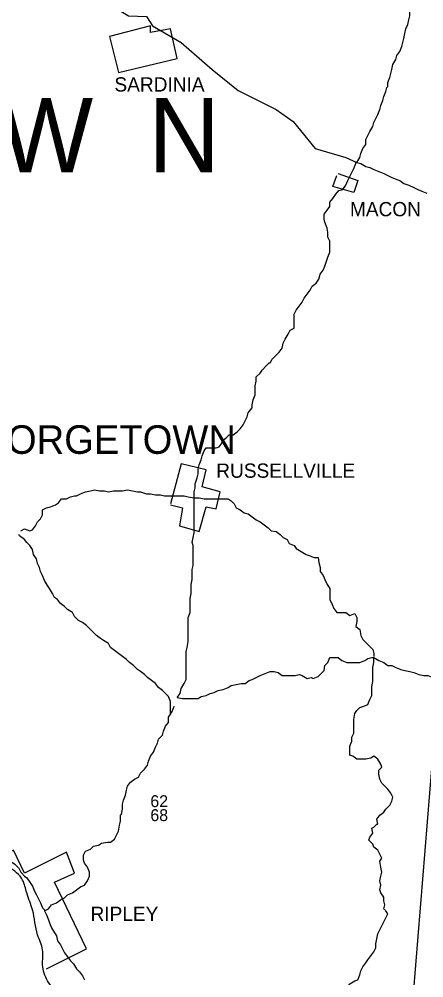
# Model space of a CAD drawing. Extents: x 0 to 34, y 0 to 22.
# Drawn here: x 3.025 to 3.578, y 16.44 to 17.75 of the extents above; entities that cross this region are included whole.
import ezdxf

# ---------------------------------------------------------------- set-up
doc = ezdxf.new("R2010")
doc.units = 0
doc.layers.add('Default', color=7, linetype='Continuous')
doc.layers.add('TR_Turning_Path1', color=7, linetype='Continuous')

msp = doc.modelspace()

# ---------------------------------------------------------------- linework, layer by layer
at = {"layer": 'Default'}
for points in [[(3.1104, 17.794), (3.1308, 17.779), (3.1499, 17.7694), (3.1744, 17.7544), (3.199, 17.7531), (3.2072, 17.7408), (3.2467, 17.7176), (3.289, 17.6808), (3.3244, 17.6522), (3.3762, 17.6263), (3.3994, 17.6099), (3.4294, 17.5731), (3.4717, 17.5608), (3.4867, 17.554)], [(3.5289, 17.6576), (3.5289, 17.6631), (3.5316, 17.6699), (3.533, 17.6754), (3.5344, 17.6808), (3.5357, 17.6876), (3.5398, 17.6945), (3.5412, 17.6999), (3.5453, 17.7054), (3.548, 17.7122), (3.5494, 17.7176), (3.5507, 17.7231), (3.5521, 17.7299), (3.5535, 17.7367), (3.5562, 17.7422), (3.5576, 17.749), (3.5589, 17.7544), (3.5589, 17.7613), (3.5603, 17.7667), (3.5603, 17.7735), (3.563, 17.7804), (3.5644, 17.7872), (3.5644, 17.7913)], [(3.6789, 17.7858), (3.6516, 17.4749), (3.5985, 16.8491), (3.5507, 16.2615), (3.5412, 16.0883), (3.5398, 16.0652)], [(3.2317, 17.7367), (3.2044, 17.7313), (3.2044, 17.7408), (3.1485, 17.7258), (3.1608, 17.6767), (3.2412, 17.6958), (3.2317, 17.7367)], [(3.4867, 17.554), (3.4907, 17.5608), (3.4921, 17.5663), (3.4948, 17.5731), (3.4989, 17.5786), (3.4989, 17.5854), (3.5017, 17.5908), (3.5044, 17.5963), (3.5085, 17.6031), (3.5098, 17.6086), (3.5126, 17.614), (3.5153, 17.6195), (3.518, 17.6263), (3.5194, 17.6317), (3.5221, 17.6386), (3.5235, 17.644), (3.5262, 17.6508), (3.5276, 17.6563), (3.5289, 17.6576)], [(3.4498, 17.4327), (3.4498, 17.4395), (3.4498, 17.4463), (3.4471, 17.4518), (3.4471, 17.4586), (3.4458, 17.464), (3.443, 17.4722), (3.4417, 17.4763), (3.4417, 17.4831), (3.4458, 17.4886), (3.4498, 17.494), (3.4498, 17.4995), (3.4539, 17.5049), (3.458, 17.5104), (3.4621, 17.5158), (3.4676, 17.5172), (3.4717, 17.5227), (3.4744, 17.5295), (3.4771, 17.5349), (3.4798, 17.5404), (3.4826, 17.5458), (3.4853, 17.5527), (3.4853, 17.554), (3.4867, 17.554)], [(3.4867, 17.554), (3.4921, 17.5527), (3.4989, 17.5486), (3.5044, 17.5472), (3.5098, 17.5445), (3.5167, 17.5418), (3.5235, 17.539), (3.5289, 17.5363), (3.5344, 17.5336), (3.5412, 17.5308), (3.5453, 17.5295), (3.5507, 17.5254), (3.5576, 17.5227), (3.5644, 17.5199), (3.5698, 17.5172), (3.5753, 17.5145), (3.5821, 17.5118)], [(3.4608, 17.539), (3.488, 17.5295), (3.4826, 17.5131), (3.4539, 17.5213), (3.4594, 17.5363)], [(3.368, 17.28), (3.3708, 17.2854), (3.3762, 17.2909), (3.3803, 17.295), (3.3844, 17.3004), (3.3858, 17.3072), (3.3885, 17.3127), (3.3926, 17.3195), (3.3953, 17.325), (3.4008, 17.3277), (3.4008, 17.3331), (3.4008, 17.34), (3.4008, 17.3468), (3.4035, 17.3522), (3.4076, 17.3577), (3.4117, 17.3631), (3.4144, 17.3686), (3.4185, 17.3741), (3.4226, 17.3795), (3.4253, 17.385), (3.4308, 17.389), (3.4348, 17.3945), (3.4362, 17.4013), (3.4403, 17.4068), (3.443, 17.4122), (3.4444, 17.4177), (3.4471, 17.4245), (3.4498, 17.4313), (3.4498, 17.4327), (3.4498, 17.4327)], [(3.3026, 17.1736), (3.308, 17.1777), (3.3121, 17.1818), (3.3176, 17.1818), (3.323, 17.1859), (3.3271, 17.19), (3.3312, 17.1954), (3.334, 17.2009), (3.3367, 17.2064), (3.338, 17.2118), (3.3435, 17.2186), (3.3435, 17.2227), (3.3449, 17.2295), (3.3476, 17.2363), (3.3476, 17.2418), (3.3476, 17.2486), (3.3489, 17.2554), (3.3489, 17.2609), (3.3544, 17.2663), (3.3571, 17.2704), (3.3626, 17.2759), (3.3667, 17.28), (3.368, 17.28)], [(3.2644, 17.0959), (3.2644, 17.1041), (3.2658, 17.1095), (3.2658, 17.115), (3.2685, 17.1232), (3.2699, 17.1286), (3.2699, 17.1355), (3.2712, 17.1409), (3.274, 17.1477), (3.2753, 17.1532), (3.2781, 17.16), (3.2808, 17.1641), (3.2876, 17.1641), (3.2944, 17.1641), (3.2985, 17.1654), (3.3026, 17.1709), (3.3026, 17.1723), (3.3026, 17.1736)], [(3.2317, 17.0864), (3.2481, 17.0823), (3.244, 17.0577), (3.2712, 17.0496), (3.2808, 17.0836), (3.2944, 17.0809), (3.2999, 17.1041), (3.2753, 17.1109), (3.2808, 17.1341), (3.2467, 17.1423), (3.2317, 17.0877)], [(3.1035, 17.0986), (3.109, 17.1014), (3.1158, 17.1041), (3.1226, 17.1055), (3.1281, 17.1068), (3.1349, 17.1055), (3.1417, 17.1055), (3.1472, 17.1041), (3.154, 17.1055), (3.1608, 17.1055), (3.1663, 17.1055), (3.1731, 17.1068), (3.1799, 17.1055), (3.1867, 17.1041), (3.1908, 17.1041), (3.199, 17.1014), (3.2044, 17.1014), (3.2112, 17.1), (3.2181, 17.1), (3.2235, 17.0986), (3.2317, 17.0986), (3.2371, 17.0986), (3.244, 17.0986), (3.2508, 17.0986), (3.2562, 17.0973), (3.2644, 17.0959), (3.2644, 17.0959)], [(3.1035, 17.0986), (3.109, 17.1014), (3.1158, 17.1041), (3.1226, 17.1055), (3.1281, 17.1068), (3.1349, 17.1055), (3.1417, 17.1055), (3.1472, 17.1041), (3.154, 17.1055), (3.1608, 17.1055), (3.1663, 17.1055), (3.1731, 17.1068), (3.1799, 17.1055), (3.1867, 17.1041), (3.1908, 17.1041), (3.199, 17.1014), (3.2044, 17.1014), (3.2112, 17.1), (3.2181, 17.1), (3.2235, 17.0986), (3.2317, 17.0986), (3.2371, 17.0986), (3.244, 17.0986), (3.2508, 17.0986), (3.2562, 17.0973), (3.2644, 17.0959), (3.2644, 17.0959)], [(3.0272, 17.0509), (3.0326, 17.0536), (3.0395, 17.0509), (3.0435, 17.0523), (3.0476, 17.0577), (3.0504, 17.0632), (3.0545, 17.0673), (3.0572, 17.0727), (3.0572, 17.0796), (3.0626, 17.0823), (3.0681, 17.0836), (3.0749, 17.0864), (3.079, 17.0891), (3.0831, 17.0946), (3.0899, 17.0946), (3.0954, 17.0973), (3.1008, 17.0986), (3.1035, 17.0986)], [(3.0272, 17.0509), (3.0326, 17.0536), (3.0395, 17.0509), (3.0435, 17.0523), (3.0476, 17.0577), (3.0504, 17.0632), (3.0545, 17.0673), (3.0572, 17.0727), (3.0572, 17.0796), (3.0626, 17.0823), (3.0681, 17.0836), (3.0749, 17.0864), (3.079, 17.0891), (3.0831, 17.0946), (3.0899, 17.0946), (3.0954, 17.0973), (3.1008, 17.0986), (3.1035, 17.0986)], [(3.2412, 16.8232), (3.2453, 16.8287), (3.2467, 16.8355), (3.2508, 16.8423), (3.2535, 16.8478), (3.2535, 16.8532), (3.2535, 16.86), (3.2535, 16.8669), (3.2535, 16.8737), (3.2535, 16.8791), (3.2535, 16.8859), (3.2549, 16.8914), (3.2562, 16.8996), (3.2562, 16.9064), (3.2562, 16.9119), (3.2562, 16.9187), (3.2562, 16.9269), (3.2562, 16.9323), (3.259, 16.9391), (3.259, 16.9446), (3.259, 16.9514), (3.259, 16.9582), (3.2603, 16.965), (3.2603, 16.9718), (3.2603, 16.9773), (3.2617, 16.9841), (3.2617, 16.9896), (3.2617, 16.9977), (3.2631, 17.0032), (3.2631, 17.0114), (3.2631, 17.0168), (3.2631, 17.0223), (3.2631, 17.0305), (3.2617, 17.0346), (3.2631, 17.0414), (3.2644, 17.0482), (3.2644, 17.055), (3.2644, 17.0618), (3.2644, 17.0673), (3.2644, 17.0741), (3.2644, 17.0809), (3.2644, 17.0877), (3.2644, 17.0946), (3.2644, 17.0959)], [(3.2644, 17.0959), (3.2712, 17.0959), (3.2781, 17.0946), (3.2835, 17.0946), (3.289, 17.0946), (3.2971, 17.0946), (3.3026, 17.0946), (3.3108, 17.0946), (3.3149, 17.0918), (3.319, 17.0877), (3.3217, 17.0823), (3.3271, 17.0796), (3.3326, 17.0755), (3.338, 17.0741), (3.3435, 17.07), (3.3489, 17.0659), (3.3544, 17.0632), (3.3599, 17.0591), (3.3653, 17.055), (3.3694, 17.0509), (3.3762, 17.0496), (3.3817, 17.0455), (3.3858, 17.0414), (3.3912, 17.0387), (3.3939, 17.0332), (3.3939, 17.0332)], [(3.1226, 16.9159), (3.1172, 16.9214), (3.1117, 16.9255), (3.1063, 16.9282), (3.1008, 16.9337), (3.0981, 16.9391), (3.0913, 16.9432), (3.0872, 16.9473), (3.0817, 16.9514), (3.0776, 16.9568), (3.0735, 16.9596), (3.0708, 16.965), (3.0667, 16.9718), (3.064, 16.9759), (3.0599, 16.9828), (3.0572, 16.9896), (3.0545, 16.995), (3.0531, 17.0005), (3.0504, 17.0059), (3.049, 17.0127), (3.0449, 17.0182), (3.0435, 17.025), (3.0395, 17.0305), (3.0354, 17.0346), (3.0326, 17.0387), (3.0258, 17.0441), (3.0245, 17.0455)], [(3.3939, 17.0332), (3.4008, 17.0305), (3.4035, 17.0264), (3.4103, 17.0223), (3.4171, 17.0182), (3.4212, 17.0168), (3.428, 17.0141), (3.4335, 17.0141), (3.4348, 17.0073), (3.4362, 17.0005), (3.4362, 16.995), (3.4403, 16.9896), (3.443, 16.9841), (3.4458, 16.9773), (3.4498, 16.9718), (3.4498, 16.965), (3.4498, 16.9637)], [(3.4498, 16.9637), (3.4498, 16.9568), (3.4526, 16.95), (3.4553, 16.9446), (3.4594, 16.9391), (3.4662, 16.9391), (3.4717, 16.9391), (3.4771, 16.935), (3.4839, 16.9378), (3.4867, 16.9323), (3.4867, 16.9269), (3.4853, 16.92), (3.4907, 16.9159), (3.4921, 16.9078), (3.4948, 16.9023), (3.4989, 16.8982), (3.503, 16.8941), (3.5085, 16.8887), (3.5098, 16.8832), (3.5098, 16.8791)], [(3.2317, 16.8001), (3.2317, 16.8055), (3.2317, 16.811), (3.2317, 16.8178), (3.229, 16.8246), (3.2249, 16.8287), (3.2208, 16.8328), (3.2153, 16.8369), (3.2112, 16.8423), (3.2058, 16.8464), (3.2003, 16.8505), (3.1962, 16.8546), (3.1908, 16.8587), (3.1867, 16.8614), (3.1812, 16.8669), (3.1758, 16.8709), (3.1717, 16.875), (3.1663, 16.8791), (3.1608, 16.8832), (3.1553, 16.8873), (3.1499, 16.8914), (3.1472, 16.8969), (3.1403, 16.9009), (3.1363, 16.9037), (3.1308, 16.9078), (3.1253, 16.9132), (3.1226, 16.9159), (3.1226, 16.9159)], [(3.4267, 16.8491), (3.4335, 16.8519), (3.4362, 16.8546), (3.4417, 16.86), (3.443, 16.8669), (3.4471, 16.8709), (3.4498, 16.8778), (3.4553, 16.8778), (3.4608, 16.8778), (3.4662, 16.8737), (3.473, 16.8709), (3.4771, 16.8709), (3.4853, 16.8709), (3.4907, 16.8709), (3.4976, 16.8737), (3.5017, 16.8764), (3.5071, 16.8778), (3.5098, 16.8778)], [(3.4771, 16.7442), (3.4771, 16.751), (3.4771, 16.7564), (3.4798, 16.7632), (3.4798, 16.7687), (3.4826, 16.7741), (3.4826, 16.781), (3.4826, 16.7878), (3.4826, 16.7932), (3.4839, 16.8014), (3.4867, 16.8055), (3.4907, 16.8096), (3.4962, 16.811), (3.5017, 16.8137), (3.5044, 16.8205), (3.5071, 16.826), (3.5071, 16.8328), (3.5071, 16.8382), (3.5085, 16.845), (3.5085, 16.8505), (3.5085, 16.8587), (3.5085, 16.8641), (3.5098, 16.8709), (3.5098, 16.8764), (3.5098, 16.8778), (3.5098, 16.8778)], [(3.5098, 16.8778), (3.5167, 16.8737), (3.5235, 16.8709), (3.5289, 16.8669), (3.5344, 16.8669), (3.5398, 16.8641), (3.5466, 16.8614), (3.5521, 16.86), (3.5589, 16.8587), (3.5644, 16.8573), (3.5712, 16.8546), (3.578, 16.8532), (3.5835, 16.8532), (3.5903, 16.8505), (3.5971, 16.8491), (3.5985, 16.8491)], [(3.3435, 16.8478), (3.3489, 16.8505), (3.3544, 16.8532), (3.3612, 16.856), (3.368, 16.8587), (3.3735, 16.8587), (3.3789, 16.8573), (3.3844, 16.8532), (3.3912, 16.8532), (3.3953, 16.8532), (3.4021, 16.8532), (3.4076, 16.8546), (3.4117, 16.8532), (3.4185, 16.8491), (3.4239, 16.8505), (3.4267, 16.8491), (3.4267, 16.8491)], [(3.2412, 16.8232), (3.2481, 16.8219), (3.2562, 16.8219), (3.2617, 16.8219), (3.2699, 16.8219), (3.274, 16.8246), (3.2808, 16.826), (3.2862, 16.8287), (3.2917, 16.83), (3.2971, 16.8328), (3.304, 16.8341), (3.3108, 16.8369), (3.3149, 16.8396), (3.3217, 16.841), (3.3285, 16.8423), (3.334, 16.8423), (3.3394, 16.8464), (3.3435, 16.8478), (3.3435, 16.8478)], [(3.2317, 16.8001), (3.2344, 16.8041), (3.2371, 16.811), (3.2371, 16.811)], [(3.1649, 16.6637), (3.1663, 16.6705), (3.1663, 16.6773), (3.1676, 16.6828), (3.1703, 16.6896), (3.1717, 16.6964), (3.1731, 16.7019), (3.1772, 16.7073), (3.1826, 16.7114), (3.1881, 16.7142), (3.1908, 16.7196), (3.1962, 16.7251), (3.2003, 16.7305), (3.2017, 16.736), (3.2044, 16.7428), (3.2085, 16.7482), (3.2112, 16.7551), (3.214, 16.7605), (3.2153, 16.766), (3.2208, 16.7714), (3.2222, 16.7769), (3.2249, 16.7837), (3.229, 16.7891), (3.229, 16.796), (3.2317, 16.8001)], [(3.1649, 16.6637), (3.1663, 16.6705), (3.1663, 16.6773), (3.1676, 16.6828), (3.1703, 16.6896), (3.1717, 16.6964), (3.1731, 16.7019), (3.1772, 16.7073), (3.1826, 16.7114), (3.1881, 16.7142), (3.1908, 16.7196), (3.1962, 16.7251), (3.2003, 16.7305), (3.2017, 16.736), (3.2044, 16.7428), (3.2085, 16.7482), (3.2112, 16.7551), (3.214, 16.7605), (3.2153, 16.766), (3.2208, 16.7714), (3.2222, 16.7769), (3.2249, 16.7837), (3.229, 16.7891), (3.229, 16.796), (3.2317, 16.8001)], [(3.5153, 16.6501), (3.5139, 16.6569), (3.518, 16.6623), (3.5235, 16.6664), (3.5262, 16.6705), (3.5316, 16.676), (3.5344, 16.6814), (3.5357, 16.6869), (3.533, 16.6923), (3.5289, 16.6978), (3.5248, 16.7019), (3.5207, 16.706), (3.518, 16.7114), (3.5167, 16.7182), (3.5167, 16.7237), (3.5207, 16.7278), (3.5194, 16.7319), (3.5153, 16.7387), (3.5098, 16.7428), (3.5057, 16.7401), (3.4989, 16.7387), (3.4935, 16.7387), (3.4867, 16.7387), (3.4812, 16.7428), (3.4771, 16.7442)], [(3.1213, 16.5846), (3.1185, 16.5914), (3.1144, 16.5969), (3.1131, 16.601), (3.1131, 16.6078), (3.1158, 16.6133), (3.1226, 16.616), (3.1267, 16.6201), (3.1335, 16.6214), (3.1376, 16.6242), (3.1458, 16.6255), (3.1499, 16.6255), (3.1553, 16.6296), (3.1581, 16.6351), (3.1608, 16.6405), (3.1622, 16.6487), (3.1635, 16.6542), (3.1635, 16.6623), (3.1649, 16.6637), (3.1649, 16.6637)], [(3.1213, 16.5846), (3.1185, 16.5914), (3.1144, 16.5969), (3.1131, 16.601), (3.1131, 16.6078), (3.1158, 16.6133), (3.1226, 16.616), (3.1267, 16.6201), (3.1335, 16.6214), (3.1376, 16.6242), (3.1458, 16.6255), (3.1499, 16.6255), (3.1553, 16.6296), (3.1581, 16.6351), (3.1608, 16.6405), (3.1622, 16.6487), (3.1635, 16.6542), (3.1635, 16.6623), (3.1649, 16.6637), (3.1649, 16.6637)], [(2.9154, 16.646), (2.9208, 16.646), (2.9277, 16.6419), (2.9345, 16.6392), (2.9399, 16.6378), (2.9454, 16.6337), (2.9522, 16.6324), (2.959, 16.631), (2.9631, 16.6283), (2.9699, 16.6242), (2.9754, 16.6214), (2.9808, 16.6174), (2.9863, 16.616), (2.9917, 16.6119), (2.9972, 16.6078), (3.0026, 16.6064), (3.0081, 16.6024), (3.0135, 16.5996), (3.019, 16.5955), (3.0245, 16.5901), (3.0272, 16.5846)], [(3.5235, 16.5342), (3.5248, 16.5396), (3.5235, 16.5451), (3.5235, 16.5505), (3.5194, 16.556), (3.518, 16.5601), (3.5194, 16.5669), (3.518, 16.5724), (3.5194, 16.5792), (3.5207, 16.5846), (3.5194, 16.5914), (3.518, 16.5996), (3.5207, 16.6037), (3.518, 16.6092), (3.5153, 16.6146), (3.5098, 16.6187), (3.5085, 16.6228), (3.503, 16.6283), (3.5044, 16.6324), (3.5085, 16.6378), (3.5071, 16.6446), (3.5098, 16.646), (3.5139, 16.6501), (3.5139, 16.6501), (3.5153, 16.6501)], [(3.0626, 16.4524), (3.1172, 16.4796), (3.0735, 16.571), (3.1008, 16.5833), (3.0899, 16.6119), (3.0326, 16.5833), (3.0176, 16.6146), (2.9931, 16.6024)], [(3.0272, 16.5846), (3.0326, 16.5792), (3.0354, 16.5765), (3.0395, 16.571), (3.0435, 16.5655), (3.0463, 16.5587), (3.049, 16.5533), (3.0517, 16.5478), (3.0545, 16.5424), (3.0572, 16.5355), (3.0599, 16.5328), (3.0599, 16.5315)], [(3.0599, 16.5315), (3.0654, 16.5342), (3.0694, 16.5396), (3.0763, 16.5424), (3.0817, 16.5465), (3.0872, 16.5492), (3.0913, 16.5533), (3.0981, 16.556), (3.1035, 16.5601), (3.109, 16.5642), (3.1144, 16.5669), (3.1185, 16.5724), (3.1213, 16.5792), (3.1213, 16.5833), (3.1213, 16.5846)], [(3.0599, 16.5315), (3.0654, 16.5342), (3.0694, 16.5396), (3.0763, 16.5424), (3.0817, 16.5465), (3.0872, 16.5492), (3.0913, 16.5533), (3.0981, 16.556), (3.1035, 16.5601), (3.109, 16.5642), (3.1144, 16.5669), (3.1185, 16.5724), (3.1213, 16.5792), (3.1213, 16.5833), (3.1213, 16.5846)], [(3.0599, 16.5315), (3.0626, 16.526), (3.0654, 16.5192), (3.0667, 16.5151), (3.0694, 16.5083), (3.0735, 16.5015), (3.0763, 16.4974), (3.0776, 16.4906), (3.0817, 16.4851), (3.0844, 16.4796), (3.0872, 16.4742), (3.0913, 16.4687), (3.0954, 16.4633), (3.0994, 16.4592), (3.1035, 16.4524), (3.1076, 16.4483), (3.1117, 16.4428), (3.1144, 16.4374)], [(3.4744, 16.4278), (3.4771, 16.4319), (3.4839, 16.436), (3.488, 16.4374), (3.4907, 16.4442), (3.4921, 16.4497), (3.4948, 16.4551), (3.4989, 16.4606), (3.5017, 16.4647), (3.5057, 16.4701), (3.5098, 16.4756), (3.5126, 16.481), (3.5126, 16.4865), (3.5139, 16.4933), (3.5153, 16.5001), (3.518, 16.5056), (3.5207, 16.511), (3.5235, 16.5165), (3.5262, 16.5219), (3.5289, 16.5274), (3.5262, 16.5315), (3.5235, 16.5342)]]:
    msp.add_lwpolyline(points, dxfattribs=at)
msp.add_spline([(3.5398, 16.0652), (3.5194, 16.0652), (3.5126, 16.0733), (3.4989, 16.0761), (3.4935, 16.0856), (3.4853, 16.0924), (3.4717, 16.0924), (3.4498, 16.1006), (3.428, 16.0979), (3.3953, 16.1047), (3.3667, 16.1143), (3.3394, 16.1183), (3.323, 16.1252), (3.3094, 16.1347), (3.3026, 16.147), (3.289, 16.1702), (3.2876, 16.1961), (3.2835, 16.2233), (3.2767, 16.2451), (3.274, 16.2765), (3.2671, 16.3106), (3.2562, 16.331), (3.2399, 16.346), (3.2208, 16.3597), (3.2044, 16.3665), (3.1799, 16.3747), (3.1499, 16.3774), (3.1267, 16.3856), (3.1131, 16.3951), (3.094, 16.4088), (3.0776, 16.4197), (3.064, 16.436), (3.0572, 16.4578), (3.0572, 16.4783), (3.0504, 16.4987), (3.0435, 16.5328), (3.0354, 16.556), (3.0299, 16.5737), (3.0108, 16.5914), (2.989, 16.6051), (2.959, 16.6228), (2.9345, 16.6324), (2.9099, 16.6446), (2.8908, 16.6514), (2.8677, 16.6542), (2.8349, 16.6583), (2.8063, 16.6651), (2.779, 16.6678), (2.7572, 16.6733), (2.7409, 16.6869), (2.7231, 16.7073), (2.7068, 16.7237), (2.6741, 16.7387), (2.64, 16.7442), (2.6032, 16.7496), (2.5609, 16.7428), (2.5391, 16.7305), (2.5118, 16.7223), (2.4709, 16.7142), (2.4464, 16.7073), (2.4191, 16.6937), (2.3864, 16.6869), (2.3577, 16.6814), (2.3373, 16.6746), (2.3168, 16.6787)], degree=3, dxfattribs=at)

# ---------------------------------------------------------------- texts
for s, height, p in [('SARDINIA', 0.0195, (3.1553, 17.6508)), ('MACON', 0.0195, (3.4771, 17.4804)), ('GEORGETOWN', 0.039, (2.9331, 17.1559)), ('RUSSELLVILLE', 0.019502, (3.2944, 17.1232)), ('62', 0.01625, (3.2044, 16.6733)), ('68', 0.01625, (3.2044, 16.6542)), ('RIPLEY', 0.0195, (3.1226, 16.5178))]:
    msp.add_text(s, height=height, dxfattribs=at).set_placement(p)
at = {"layer": 'TR_Turning_Path1'}
msp.add_text('B  R  O  W  N', height=0.101489, dxfattribs=at).set_placement((2.4777, 17.5404))

doc.saveas('drawing.dxf')
